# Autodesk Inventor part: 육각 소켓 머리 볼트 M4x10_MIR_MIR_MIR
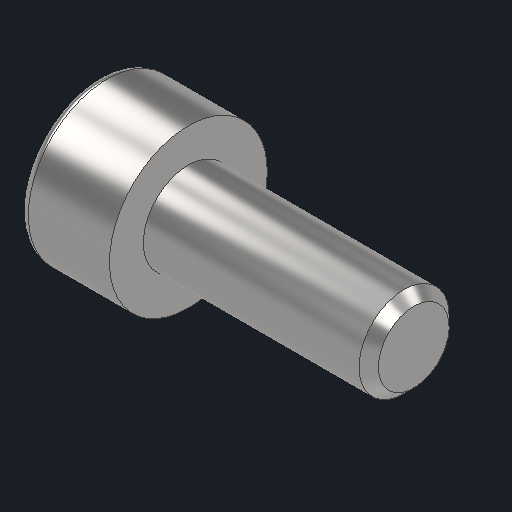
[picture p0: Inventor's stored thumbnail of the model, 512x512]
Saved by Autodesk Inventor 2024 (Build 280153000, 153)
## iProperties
Created: 2024-05
Part Number: 육각 소켓 머리 볼트 M4x10_MIR_MIR_MIR
Material: 강철, 연강
Description: 6각머리 태핑 나사
Document SubType Name: Modeling
Designer: kh_501
Density: 7.85 g/cm^3
Appearance: 기본값
Author: jhkim
Sending System: Autodesk Inventor 2025
Preprocessor: ST-DEVELOPER v20
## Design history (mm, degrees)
derived "육각 소켓 머리 볼트 M4x10_MIR_MIR.ipt"
feature "솔리드1::육각 소켓 머리 볼트 M4x10_MIR_MIR.ipt" dims "d0" = 10
tag "피쳐 태그1"
node "솔리드1"
